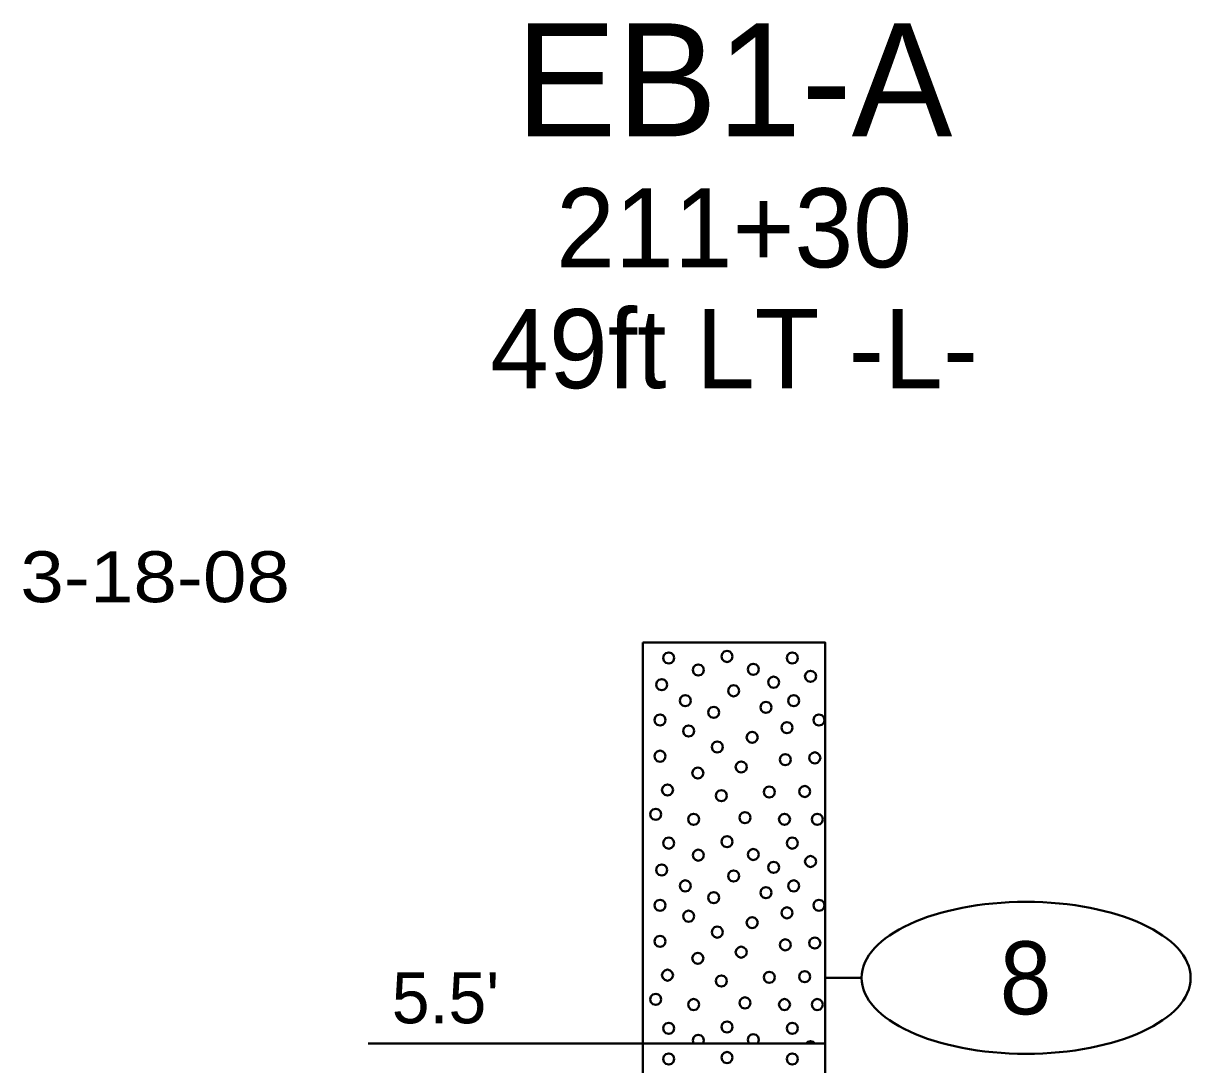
# Model space of a CAD drawing. Extents: x -582 to 653, y -817 to -3.
# Drawn here: x -582.24 to -566.23, y -187.1 to -172.82 of the extents above; entities that cross this region are included whole.
import ezdxf
from ezdxf.enums import TextEntityAlignment as Align

# ---------------------------------------------------------------- set-up
doc = ezdxf.new("R2010")
doc.units = 0
doc.header["$LTSCALE"] = 0.4
doc.layers.add('27', color=7, linetype='Continuous', lineweight=40)

msp = doc.modelspace()

# ---------------------------------------------------------------- linework, layer by layer
at = {"layer": '27'}
for p, q in [((-570.7477, -185.908), (-571.2477, -185.908)), ((-577.5151, -186.808), (-573.7477, -186.808))]:
    msp.add_line(p, q, dxfattribs=at)
for points in [[(-573.7477, -181.308), (-571.2477, -181.308), (-571.2477, -186.808), (-573.7477, -186.808)], [(-573.3158, -181.5207), (-573.326, -181.4826), (-573.3539, -181.4547), (-573.392, -181.4445), (-573.4301, -181.4547), (-573.458, -181.4826), (-573.4682, -181.5207), (-573.458, -181.5588), (-573.4301, -181.5867), (-573.392, -181.5969), (-573.3539, -181.5867), (-573.326, -181.5588)], [(-572.5148, -181.5011), (-572.525, -181.463), (-572.5529, -181.4351), (-572.591, -181.4249), (-572.6291, -181.4351), (-572.657, -181.463), (-572.6672, -181.5011), (-572.657, -181.5392), (-572.6291, -181.5671), (-572.591, -181.5773), (-572.5529, -181.5671), (-572.525, -181.5392)], [(-571.6212, -181.5207), (-571.6314, -181.4826), (-571.6593, -181.4548), (-571.6974, -181.4445), (-571.7355, -181.4548), (-571.7634, -181.4826), (-571.7736, -181.5207), (-571.7634, -181.5588), (-571.7355, -181.5867), (-571.6974, -181.5969), (-571.6593, -181.5867), (-571.6314, -181.5588)], [(-572.9108, -181.686), (-572.921, -181.6479), (-572.9489, -181.62), (-572.987, -181.6098), (-573.0251, -181.62), (-573.053, -181.6479), (-573.0632, -181.686), (-573.053, -181.7241), (-573.0251, -181.7519), (-572.987, -181.7622), (-572.9489, -181.7519), (-572.921, -181.7241)], [(-572.1558, -181.677), (-572.166, -181.6389), (-572.1939, -181.611), (-572.232, -181.6008), (-572.2701, -181.611), (-572.2979, -181.6389), (-572.3082, -181.677), (-572.2979, -181.7151), (-572.2701, -181.743), (-572.232, -181.7532), (-572.1939, -181.743), (-572.166, -181.7151)], [(-571.3703, -181.7728), (-571.3805, -181.7347), (-571.4084, -181.7069), (-571.4465, -181.6966), (-571.4846, -181.7069), (-571.5125, -181.7347), (-571.5227, -181.7728), (-571.5125, -181.8109), (-571.4846, -181.8388), (-571.4465, -181.849), (-571.4084, -181.8388), (-571.3805, -181.8109)], [(-573.412, -181.8885), (-573.4222, -181.8504), (-573.4501, -181.8225), (-573.4882, -181.8123), (-573.5263, -181.8225), (-573.5541, -181.8504), (-573.5644, -181.8885), (-573.5541, -181.9266), (-573.5263, -181.9545), (-573.4882, -181.9647), (-573.4501, -181.9545), (-573.4222, -181.9266)], [(-571.8775, -181.8542), (-571.8877, -181.8161), (-571.9156, -181.7882), (-571.9537, -181.778), (-571.9918, -181.7882), (-572.0197, -181.8161), (-572.0299, -181.8542), (-572.0197, -181.8923), (-571.9918, -181.9202), (-571.9537, -181.9304), (-571.9156, -181.9202), (-571.8877, -181.8923)], [(-573.0891, -182.1072), (-573.0993, -182.0691), (-573.1272, -182.0412), (-573.1653, -182.031), (-573.2034, -182.0412), (-573.2312, -182.0691), (-573.2415, -182.1072), (-573.2312, -182.1453), (-573.2034, -182.1732), (-573.1653, -182.1834), (-573.1272, -182.1732), (-573.0993, -182.1453)], [(-572.4259, -181.9717), (-572.4361, -181.9336), (-572.464, -181.9057), (-572.5021, -181.8955), (-572.5402, -181.9057), (-572.5681, -181.9336), (-572.5783, -181.9717), (-572.5681, -182.0098), (-572.5402, -182.0377), (-572.5021, -182.0479), (-572.464, -182.0377), (-572.4361, -182.0098)], [(-571.6004, -182.1072), (-571.6106, -182.0691), (-571.6385, -182.0412), (-571.6766, -182.031), (-571.7147, -182.0412), (-571.7426, -182.0691), (-571.7528, -182.1072), (-571.7426, -182.1453), (-571.7147, -182.1732), (-571.6766, -182.1834), (-571.6385, -182.1732), (-571.6106, -182.1453)], [(-572.6975, -182.2686), (-572.7077, -182.2305), (-572.7356, -182.2027), (-572.7737, -182.1924), (-572.8118, -182.2027), (-572.8397, -182.2305), (-572.8499, -182.2686), (-572.8397, -182.3067), (-572.8118, -182.3346), (-572.7737, -182.3448), (-572.7356, -182.3346), (-572.7077, -182.3067)], [(-571.9818, -182.2), (-571.992, -182.1619), (-572.0199, -182.134), (-572.058, -182.1238), (-572.0961, -182.134), (-572.124, -182.1619), (-572.1342, -182.2), (-572.124, -182.2381), (-572.0961, -182.266), (-572.058, -182.2762), (-572.0199, -182.266), (-571.992, -182.2381)], [(-573.4348, -182.3729), (-573.4451, -182.3348), (-573.4729, -182.3069), (-573.511, -182.2967), (-573.5491, -182.3069), (-573.577, -182.3348), (-573.5872, -182.3729), (-573.577, -182.411), (-573.5491, -182.4389), (-573.511, -182.4491), (-573.4729, -182.4389), (-573.4451, -182.411)], [(-571.2546, -182.3729), (-571.2648, -182.3348), (-571.2927, -182.3069), (-571.3308, -182.2967), (-571.3689, -182.3069), (-571.3968, -182.3348), (-571.407, -182.3729), (-571.3968, -182.411), (-571.3689, -182.4389), (-571.3308, -182.4491), (-571.2927, -182.4389), (-571.2648, -182.411)], [(-573.0433, -182.5229), (-573.0535, -182.4848), (-573.0814, -182.4569), (-573.1195, -182.4467), (-573.1576, -182.4569), (-573.1855, -182.4848), (-573.1957, -182.5229), (-573.1855, -182.561), (-573.1576, -182.5889), (-573.1195, -182.5991), (-573.0814, -182.5889), (-573.0535, -182.561)], [(-571.6932, -182.4771), (-571.7034, -182.439), (-571.7313, -182.4111), (-571.7694, -182.4009), (-571.8075, -182.4111), (-571.8354, -182.439), (-571.8456, -182.4771), (-571.8354, -182.5152), (-571.8075, -182.5431), (-571.7694, -182.5533), (-571.7313, -182.5431), (-571.7034, -182.5152)], [(-572.6492, -182.7416), (-572.6594, -182.7035), (-572.6873, -182.6756), (-572.7254, -182.6654), (-572.7635, -182.6756), (-572.7914, -182.7035), (-572.8016, -182.7416), (-572.7914, -182.7797), (-572.7635, -182.8075), (-572.7254, -182.8178), (-572.6873, -182.8075), (-572.6594, -182.7797)], [(-572.1712, -182.6106), (-572.1814, -182.5725), (-572.2093, -182.5446), (-572.2474, -182.5344), (-572.2855, -182.5446), (-572.3134, -182.5725), (-572.3236, -182.6106), (-572.3134, -182.6487), (-572.2855, -182.6766), (-572.2474, -182.6868), (-572.2093, -182.6766), (-572.1814, -182.6487)], [(-573.4348, -182.8687), (-573.4451, -182.8306), (-573.4729, -182.8027), (-573.511, -182.7925), (-573.5491, -182.8027), (-573.577, -182.8306), (-573.5872, -182.8687), (-573.577, -182.9068), (-573.5491, -182.9347), (-573.511, -182.9449), (-573.4729, -182.9347), (-573.4451, -182.9068)], [(-571.7161, -182.9157), (-571.7263, -182.8776), (-571.7542, -182.8497), (-571.7923, -182.8395), (-571.8304, -182.8497), (-571.8583, -182.8776), (-571.8685, -182.9157), (-571.8583, -182.9538), (-571.8304, -182.9817), (-571.7923, -182.9919), (-571.7542, -182.9817), (-571.7263, -182.9538)], [(-571.3118, -182.8916), (-571.322, -182.8535), (-571.3499, -182.8256), (-571.388, -182.8154), (-571.4261, -182.8256), (-571.454, -182.8535), (-571.4642, -182.8916), (-571.454, -182.9297), (-571.4261, -182.9576), (-571.388, -182.9678), (-571.3499, -182.9576), (-571.322, -182.9297)], [(-572.3212, -183.0161), (-572.3314, -182.978), (-572.3593, -182.9502), (-572.3974, -182.9399), (-572.4355, -182.9502), (-572.4634, -182.978), (-572.4736, -183.0161), (-572.4634, -183.0542), (-572.4355, -183.0821), (-572.3974, -183.0923), (-572.3593, -183.0821), (-572.3314, -183.0542)], [(-572.9162, -183.1001), (-572.9264, -183.062), (-572.9543, -183.0341), (-572.9924, -183.0239), (-573.0305, -183.0341), (-573.0584, -183.062), (-573.0686, -183.1001), (-573.0584, -183.1382), (-573.0305, -183.166), (-572.9924, -183.1763), (-572.9543, -183.166), (-572.9264, -183.1382)], [(-573.3319, -183.3314), (-573.3421, -183.2933), (-573.37, -183.2654), (-573.4081, -183.2552), (-573.4462, -183.2654), (-573.4741, -183.2933), (-573.4843, -183.3314), (-573.4741, -183.3695), (-573.4462, -183.3974), (-573.4081, -183.4076), (-573.37, -183.3974), (-573.3421, -183.3695)], [(-571.936, -183.3607), (-571.9462, -183.3226), (-571.9741, -183.2947), (-572.0122, -183.2845), (-572.0503, -183.2947), (-572.0782, -183.3226), (-572.0884, -183.3607), (-572.0782, -183.3988), (-572.0503, -183.4267), (-572.0122, -183.4369), (-571.9741, -183.4267), (-571.9462, -183.3988)], [(-571.4504, -183.353), (-571.4606, -183.3149), (-571.4885, -183.287), (-571.5266, -183.2768), (-571.5647, -183.287), (-571.5926, -183.3149), (-571.6028, -183.353), (-571.5926, -183.3911), (-571.5647, -183.419), (-571.5266, -183.4292), (-571.4885, -183.419), (-571.4606, -183.3911)], [(-572.5933, -183.4115), (-572.6035, -183.3734), (-572.6314, -183.3455), (-572.6695, -183.3353), (-572.7076, -183.3455), (-572.7355, -183.3734), (-572.7457, -183.4115), (-572.7355, -183.4496), (-572.7076, -183.4775), (-572.6695, -183.4877), (-572.6314, -183.4775), (-572.6035, -183.4496)], [(-573.4933, -183.6645), (-573.5035, -183.6264), (-573.5314, -183.5985), (-573.5695, -183.5883), (-573.6076, -183.5985), (-573.6355, -183.6264), (-573.6457, -183.6645), (-573.6355, -183.7026), (-573.6076, -183.7305), (-573.5695, -183.7407), (-573.5314, -183.7305), (-573.5035, -183.7026)], [(-572.2704, -183.7115), (-572.2806, -183.6734), (-572.3085, -183.6455), (-572.3466, -183.6353), (-572.3847, -183.6455), (-572.4125, -183.6734), (-572.4228, -183.7115), (-572.4125, -183.7496), (-572.3847, -183.7775), (-572.3466, -183.7877), (-572.3085, -183.7775), (-572.2806, -183.7496)], [(-572.9746, -183.7344), (-572.9848, -183.6963), (-573.0127, -183.6684), (-573.0508, -183.6582), (-573.0889, -183.6684), (-573.1168, -183.6963), (-573.127, -183.7344), (-573.1168, -183.7725), (-573.0889, -183.8004), (-573.0508, -183.8106), (-573.0127, -183.8004), (-572.9848, -183.7725)], [(-571.7275, -183.7344), (-571.7377, -183.6963), (-571.7656, -183.6684), (-571.8037, -183.6582), (-571.8418, -183.6684), (-571.8697, -183.6963), (-571.8799, -183.7344), (-571.8697, -183.7725), (-571.8418, -183.8004), (-571.8037, -183.8106), (-571.7656, -183.8004), (-571.7377, -183.7725)], [(-571.2775, -183.7344), (-571.2877, -183.6963), (-571.3156, -183.6684), (-571.3537, -183.6582), (-571.3918, -183.6684), (-571.4197, -183.6963), (-571.4299, -183.7344), (-571.4197, -183.7725), (-571.3918, -183.8004), (-571.3537, -183.8106), (-571.3156, -183.8004), (-571.2877, -183.7725)], [(-573.3158, -184.0607), (-573.326, -184.0226), (-573.3539, -183.9947), (-573.392, -183.9845), (-573.4301, -183.9947), (-573.458, -184.0226), (-573.4682, -184.0607), (-573.458, -184.0988), (-573.4301, -184.1267), (-573.392, -184.1369), (-573.3539, -184.1267), (-573.326, -184.0988)], [(-572.5148, -184.0411), (-572.525, -184.003), (-572.5529, -183.9751), (-572.591, -183.9649), (-572.6291, -183.9751), (-572.657, -184.003), (-572.6672, -184.0411), (-572.657, -184.0792), (-572.6291, -184.1071), (-572.591, -184.1173), (-572.5529, -184.1071), (-572.525, -184.0792)], [(-571.6212, -184.0607), (-571.6314, -184.0226), (-571.6593, -183.9948), (-571.6974, -183.9845), (-571.7355, -183.9948), (-571.7634, -184.0226), (-571.7736, -184.0607), (-571.7634, -184.0988), (-571.7355, -184.1267), (-571.6974, -184.1369), (-571.6593, -184.1267), (-571.6314, -184.0988)], [(-572.9108, -184.226), (-572.921, -184.1879), (-572.9489, -184.16), (-572.987, -184.1498), (-573.0251, -184.16), (-573.053, -184.1879), (-573.0632, -184.226), (-573.053, -184.2641), (-573.0251, -184.2919), (-572.987, -184.3022), (-572.9489, -184.2919), (-572.921, -184.2641)], [(-572.1558, -184.217), (-572.166, -184.1789), (-572.1939, -184.151), (-572.232, -184.1408), (-572.2701, -184.151), (-572.2979, -184.1789), (-572.3082, -184.217), (-572.2979, -184.2551), (-572.2701, -184.283), (-572.232, -184.2932), (-572.1939, -184.283), (-572.166, -184.2551)], [(-571.3703, -184.3128), (-571.3805, -184.2747), (-571.4084, -184.2469), (-571.4465, -184.2366), (-571.4846, -184.2469), (-571.5125, -184.2747), (-571.5227, -184.3128), (-571.5125, -184.3509), (-571.4846, -184.3788), (-571.4465, -184.389), (-571.4084, -184.3788), (-571.3805, -184.3509)], [(-573.412, -184.4285), (-573.4222, -184.3904), (-573.4501, -184.3625), (-573.4882, -184.3523), (-573.5263, -184.3625), (-573.5541, -184.3904), (-573.5644, -184.4285), (-573.5541, -184.4666), (-573.5263, -184.4945), (-573.4882, -184.5047), (-573.4501, -184.4945), (-573.4222, -184.4666)], [(-572.4259, -184.5117), (-572.4361, -184.4736), (-572.464, -184.4457), (-572.5021, -184.4355), (-572.5402, -184.4457), (-572.5681, -184.4736), (-572.5783, -184.5117), (-572.5681, -184.5498), (-572.5402, -184.5777), (-572.5021, -184.5879), (-572.464, -184.5777), (-572.4361, -184.5498)], [(-571.8775, -184.3942), (-571.8877, -184.3561), (-571.9156, -184.3282), (-571.9537, -184.318), (-571.9918, -184.3282), (-572.0197, -184.3561), (-572.0299, -184.3942), (-572.0197, -184.4323), (-571.9918, -184.4602), (-571.9537, -184.4704), (-571.9156, -184.4602), (-571.8877, -184.4323)], [(-573.0891, -184.6472), (-573.0993, -184.6091), (-573.1272, -184.5812), (-573.1653, -184.571), (-573.2034, -184.5812), (-573.2312, -184.6091), (-573.2415, -184.6472), (-573.2312, -184.6853), (-573.2034, -184.7132), (-573.1653, -184.7234), (-573.1272, -184.7132), (-573.0993, -184.6853)], [(-571.6004, -184.6472), (-571.6106, -184.6091), (-571.6385, -184.5812), (-571.6766, -184.571), (-571.7147, -184.5812), (-571.7426, -184.6091), (-571.7528, -184.6472), (-571.7426, -184.6853), (-571.7147, -184.7132), (-571.6766, -184.7234), (-571.6385, -184.7132), (-571.6106, -184.6853)], [(-572.6975, -184.8086), (-572.7077, -184.7705), (-572.7356, -184.7427), (-572.7737, -184.7324), (-572.8118, -184.7427), (-572.8397, -184.7705), (-572.8499, -184.8086), (-572.8397, -184.8467), (-572.8118, -184.8746), (-572.7737, -184.8848), (-572.7356, -184.8746), (-572.7077, -184.8467)], [(-571.9818, -184.74), (-571.992, -184.7019), (-572.0199, -184.674), (-572.058, -184.6638), (-572.0961, -184.674), (-572.124, -184.7019), (-572.1342, -184.74), (-572.124, -184.7781), (-572.0961, -184.806), (-572.058, -184.8162), (-572.0199, -184.806), (-571.992, -184.7781)], [(-573.4348, -184.9129), (-573.4451, -184.8748), (-573.4729, -184.8469), (-573.511, -184.8367), (-573.5491, -184.8469), (-573.577, -184.8748), (-573.5872, -184.9129), (-573.577, -184.951), (-573.5491, -184.9789), (-573.511, -184.9891), (-573.4729, -184.9789), (-573.4451, -184.951)], [(-571.2546, -184.9129), (-571.2648, -184.8748), (-571.2927, -184.8469), (-571.3308, -184.8367), (-571.3689, -184.8469), (-571.3968, -184.8748), (-571.407, -184.9129), (-571.3968, -184.951), (-571.3689, -184.9789), (-571.3308, -184.9891), (-571.2927, -184.9789), (-571.2648, -184.951)], [(-573.0433, -185.0629), (-573.0535, -185.0248), (-573.0814, -184.9969), (-573.1195, -184.9867), (-573.1576, -184.9969), (-573.1855, -185.0248), (-573.1957, -185.0629), (-573.1855, -185.101), (-573.1576, -185.1289), (-573.1195, -185.1391), (-573.0814, -185.1289), (-573.0535, -185.101)], [(-572.1712, -185.1506), (-572.1814, -185.1125), (-572.2093, -185.0846), (-572.2474, -185.0744), (-572.2855, -185.0846), (-572.3134, -185.1125), (-572.3236, -185.1506), (-572.3134, -185.1887), (-572.2855, -185.2166), (-572.2474, -185.2268), (-572.2093, -185.2166), (-572.1814, -185.1887)], [(-571.6932, -185.0171), (-571.7034, -184.979), (-571.7313, -184.9511), (-571.7694, -184.9409), (-571.8075, -184.9511), (-571.8354, -184.979), (-571.8456, -185.0171), (-571.8354, -185.0552), (-571.8075, -185.0831), (-571.7694, -185.0933), (-571.7313, -185.0831), (-571.7034, -185.0552)], [(-572.6492, -185.2816), (-572.6594, -185.2435), (-572.6873, -185.2156), (-572.7254, -185.2054), (-572.7635, -185.2156), (-572.7914, -185.2435), (-572.8016, -185.2816), (-572.7914, -185.3197), (-572.7635, -185.3475), (-572.7254, -185.3578), (-572.6873, -185.3475), (-572.6594, -185.3197)], [(-573.4348, -185.4087), (-573.4451, -185.3706), (-573.4729, -185.3427), (-573.511, -185.3325), (-573.5491, -185.3427), (-573.577, -185.3706), (-573.5872, -185.4087), (-573.577, -185.4468), (-573.5491, -185.4747), (-573.511, -185.4849), (-573.4729, -185.4747), (-573.4451, -185.4468)], [(-571.7161, -185.4557), (-571.7263, -185.4176), (-571.7542, -185.3897), (-571.7923, -185.3795), (-571.8304, -185.3897), (-571.8583, -185.4176), (-571.8685, -185.4557), (-571.8583, -185.4938), (-571.8304, -185.5217), (-571.7923, -185.5319), (-571.7542, -185.5217), (-571.7263, -185.4938)], [(-571.3118, -185.4316), (-571.322, -185.3935), (-571.3499, -185.3656), (-571.388, -185.3554), (-571.4261, -185.3656), (-571.454, -185.3935), (-571.4642, -185.4316), (-571.454, -185.4697), (-571.4261, -185.4976), (-571.388, -185.5078), (-571.3499, -185.4976), (-571.322, -185.4697)], [(-572.3212, -185.5561), (-572.3314, -185.518), (-572.3593, -185.4902), (-572.3974, -185.4799), (-572.4355, -185.4902), (-572.4634, -185.518), (-572.4736, -185.5561), (-572.4634, -185.5942), (-572.4355, -185.6221), (-572.3974, -185.6323), (-572.3593, -185.6221), (-572.3314, -185.5942)], [(-572.9162, -185.6401), (-572.9264, -185.602), (-572.9543, -185.5741), (-572.9924, -185.5639), (-573.0305, -185.5741), (-573.0584, -185.602), (-573.0686, -185.6401), (-573.0584, -185.6782), (-573.0305, -185.706), (-572.9924, -185.7163), (-572.9543, -185.706), (-572.9264, -185.6782)], [(-573.3319, -185.8714), (-573.3421, -185.8333), (-573.37, -185.8054), (-573.4081, -185.7952), (-573.4462, -185.8054), (-573.4741, -185.8333), (-573.4843, -185.8714), (-573.4741, -185.9095), (-573.4462, -185.9374), (-573.4081, -185.9476), (-573.37, -185.9374), (-573.3421, -185.9095)], [(-572.5933, -185.9515), (-572.6035, -185.9134), (-572.6314, -185.8855), (-572.6695, -185.8753), (-572.7076, -185.8855), (-572.7355, -185.9134), (-572.7457, -185.9515), (-572.7355, -185.9896), (-572.7076, -186.0175), (-572.6695, -186.0277), (-572.6314, -186.0175), (-572.6035, -185.9896)], [(-571.936, -185.9007), (-571.9462, -185.8626), (-571.9741, -185.8347), (-572.0122, -185.8245), (-572.0503, -185.8347), (-572.0782, -185.8626), (-572.0884, -185.9007), (-572.0782, -185.9388), (-572.0503, -185.9667), (-572.0122, -185.9769), (-571.9741, -185.9667), (-571.9462, -185.9388)], [(-571.4504, -185.893), (-571.4606, -185.8549), (-571.4885, -185.827), (-571.5266, -185.8168), (-571.5647, -185.827), (-571.5926, -185.8549), (-571.6028, -185.893), (-571.5926, -185.9311), (-571.5647, -185.959), (-571.5266, -185.9692), (-571.4885, -185.959), (-571.4606, -185.9311)], [(-573.4933, -186.2045), (-573.5035, -186.1664), (-573.5314, -186.1385), (-573.5695, -186.1283), (-573.6076, -186.1385), (-573.6355, -186.1664), (-573.6457, -186.2045), (-573.6355, -186.2426), (-573.6076, -186.2705), (-573.5695, -186.2807), (-573.5314, -186.2705), (-573.5035, -186.2426)], [(-572.9746, -186.2744), (-572.9848, -186.2363), (-573.0127, -186.2084), (-573.0508, -186.1982), (-573.0889, -186.2084), (-573.1168, -186.2363), (-573.127, -186.2744), (-573.1168, -186.3125), (-573.0889, -186.3404), (-573.0508, -186.3506), (-573.0127, -186.3404), (-572.9848, -186.3125)], [(-572.2704, -186.2515), (-572.2806, -186.2134), (-572.3085, -186.1855), (-572.3466, -186.1753), (-572.3847, -186.1855), (-572.4125, -186.2134), (-572.4228, -186.2515), (-572.4125, -186.2896), (-572.3847, -186.3175), (-572.3466, -186.3277), (-572.3085, -186.3175), (-572.2806, -186.2896)], [(-571.7275, -186.2744), (-571.7377, -186.2363), (-571.7656, -186.2084), (-571.8037, -186.1982), (-571.8418, -186.2084), (-571.8697, -186.2363), (-571.8799, -186.2744), (-571.8697, -186.3125), (-571.8418, -186.3404), (-571.8037, -186.3506), (-571.7656, -186.3404), (-571.7377, -186.3125)], [(-571.2775, -186.2744), (-571.2877, -186.2363), (-571.3156, -186.2084), (-571.3537, -186.1982), (-571.3918, -186.2084), (-571.4197, -186.2363), (-571.4299, -186.2744), (-571.4197, -186.3125), (-571.3918, -186.3404), (-571.3537, -186.3506), (-571.3156, -186.3404), (-571.2877, -186.3125)], [(-572.5148, -186.5811), (-572.525, -186.543), (-572.5529, -186.5151), (-572.591, -186.5049), (-572.6291, -186.5151), (-572.657, -186.543), (-572.6672, -186.5811), (-572.657, -186.6192), (-572.6291, -186.6471), (-572.591, -186.6573), (-572.5529, -186.6471), (-572.525, -186.6192)], [(-573.3158, -186.6007), (-573.326, -186.5626), (-573.3539, -186.5347), (-573.392, -186.5245), (-573.4301, -186.5347), (-573.458, -186.5626), (-573.4682, -186.6007), (-573.458, -186.6388), (-573.4301, -186.6667), (-573.392, -186.6769), (-573.3539, -186.6667), (-573.326, -186.6388)], [(-572.166, -186.7951), (-572.1558, -186.757), (-572.166, -186.7189), (-572.1939, -186.691), (-572.232, -186.6808), (-572.2701, -186.691), (-572.2979, -186.7189), (-572.3082, -186.757), (-572.2979, -186.7951), (-572.285, -186.808), (-572.179, -186.808)], [(-571.6212, -186.6007), (-571.6314, -186.5626), (-571.6593, -186.5348), (-571.6974, -186.5245), (-571.7355, -186.5348), (-571.7634, -186.5626), (-571.7736, -186.6007), (-571.7634, -186.6388), (-571.7355, -186.6667), (-571.6974, -186.6769), (-571.6593, -186.6667), (-571.6314, -186.6388)], [(-573.7477, -186.808), (-571.2477, -186.808), (-571.2477, -192.308), (-573.7477, -192.308)], [(-572.921, -186.8041), (-572.9108, -186.766), (-572.921, -186.7279), (-572.9489, -186.7), (-572.987, -186.6898), (-573.0251, -186.7), (-573.053, -186.7279), (-573.0632, -186.766), (-573.053, -186.8041), (-573.049, -186.808), (-572.925, -186.808)], [(-571.4084, -186.7869), (-571.4465, -186.7766), (-571.4846, -186.7869), (-571.5058, -186.808), (-571.3872, -186.808)], [(-573.3158, -187.0207), (-573.326, -186.9826), (-573.3539, -186.9547), (-573.392, -186.9445), (-573.4301, -186.9547), (-573.458, -186.9826), (-573.4682, -187.0207), (-573.458, -187.0588), (-573.4301, -187.0867), (-573.392, -187.0969), (-573.3539, -187.0867), (-573.326, -187.0588)], [(-572.5148, -187.0011), (-572.525, -186.963), (-572.5529, -186.9351), (-572.591, -186.9249), (-572.6291, -186.9351), (-572.657, -186.963), (-572.6672, -187.0011), (-572.657, -187.0392), (-572.6291, -187.0671), (-572.591, -187.0773), (-572.5529, -187.0671), (-572.525, -187.0392)], [(-571.6212, -187.0207), (-571.6314, -186.9826), (-571.6593, -186.9548), (-571.6974, -186.9445), (-571.7355, -186.9548), (-571.7634, -186.9826), (-571.7736, -187.0207), (-571.7634, -187.0588), (-571.7355, -187.0867), (-571.6974, -187.0969), (-571.6593, -187.0867), (-571.6314, -187.0588)]]:
    msp.add_lwpolyline(points, close=True, dxfattribs=at)
msp.add_ellipse((-568.4903, -185.908), major_axis=(2.2574, 0), ratio=0.461538, dxfattribs=at)

# ---------------------------------------------------------------- texts
for s, height, p in [('EB1-A', 1.55, (-572.4959, -174.3685)), ('211+30', 1.085, (-572.495, -176.1649)), ('49ft LT -L-', 1.085, (-572.4955, -177.8219))]:
    msp.add_text(s, height=height, dxfattribs=at).set_placement(p, align=Align.CENTER)
for s, height, width, p in [('3-18-08', 0.6976, 1.15, (-580.4355, -180.7565)), ('8', 1, 0.95, (-568.4976, -186.408))]:
    msp.add_text(s, height=height, dxfattribs=dict(at, width=width)).set_placement(p, align=Align.CENTER)
msp.add_text("5.5'", height=0.6976, dxfattribs=at).set_placement((-577.191, -186.5316))

doc.saveas('drawing.dxf')
